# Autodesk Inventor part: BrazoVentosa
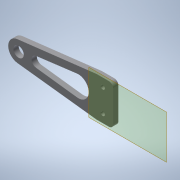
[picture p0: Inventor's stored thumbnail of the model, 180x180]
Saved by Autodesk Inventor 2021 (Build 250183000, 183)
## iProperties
Created: 2021-02
Part Number: BrazoVentosa
Material: Genérico
Document SubType Name: Modeling
Designer: ATOUZA
Density: 1 g/cm^3
Appearance: Valor por defecto
Author: ATOUZA
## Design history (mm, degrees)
node "Plano de trabajo1"
sketch "Boceto1"
  geometry: L1 (30, 19)-(-30, 19) reference; L2 (-34, 15)-(-34, -15) reference; L3 (-30, -19)-(30, -19) reference; L4 (34, -15)-(34, 15) reference; L5 (122.5, -17.5)-(122.5, 17.5) reference; L6 (122.5, 17.5)-(87.5, 17.5) reference; L7 (87.5, 17.5)-(87.5, -17.5) reference; L8 (87.5, -17.5)-(122.5, -17.5) reference; L9 (30, 19)-(106.182, 9.93); L10 (30, -19)-(106.182, -9.93); L11 (14, 19)-(14, -19); L12 (14, 19)-(30, 19); L13 (14, -19)-(30, -19); L14 (48.76, 9.96)-(88.13, 4.96); L15 (48.74, -9.883)-(88.12, -4.961); C1 r 2 at (24, -11) reference; C2 r 2 at (24, 11) reference; C3 r 2.5 at (-7.222, -7.778) reference; C4 r 2.5 at (-22.778, 7.778) reference; C5 r 5 at (105, 0); C6 r 2 at (24, 11); C7 r 2 at (24, -11); C8 r 3 at (-15, 0) reference; A1 r 4 centre (30, 15) between (34, 15) and (30, 19) reference; A2 r 4 centre (-30, 15) between (-30, 19) and (-34, 15) reference; A3 r 4 centre (-30, -15) between (-34, -15) and (-30, -19) reference; A4 r 4 centre (30, -15) between (30, -19) and (34, -15) reference; A5 r 10 centre (105, 0) between (106.182, -9.93) and (106.182, 9.93); A6 r 5 centre (87.5, 0) between (87.5, -5) and (87.5, 5); A7 r 10 centre (47.5, 0.04) between (48.76, 9.96) and (48.74, -9.883); A8 r 10 centre (47.5, 0.04) between (48.76, 9.96) and (48.74, -9.883); A9 r 5 centre (87.5, 0) between (87.5, -5) and (87.5, 5); 1 further point
  constraints: 14 end point, 12 point on circle, 8 centre point, 7 tangent, 5 coincident, 4 concentric, 4 point on line, 1 horizontal, 1 midpoint, 1 parallel, 1 perpendicular
  dimensions: "d0" = 10 diameter of C5; "d1" = 20 diameter of A5; "d2" = 20 distance between parallel lines of L11 L4; "d3" = 10 diameter of A6; "d4" = 20 diameter of A7; "d5" = 40 distance of A6.centre A7.centre
extrude "Extrusión1" new body sketch "Boceto1" distance "d6" = 5; taper "d7" = 0 deg
fillet "Empalme1" dims "d8" = 4
node "Sólido1"
node "Referencia1"
node "Referencia2"
node "Referencia3"
